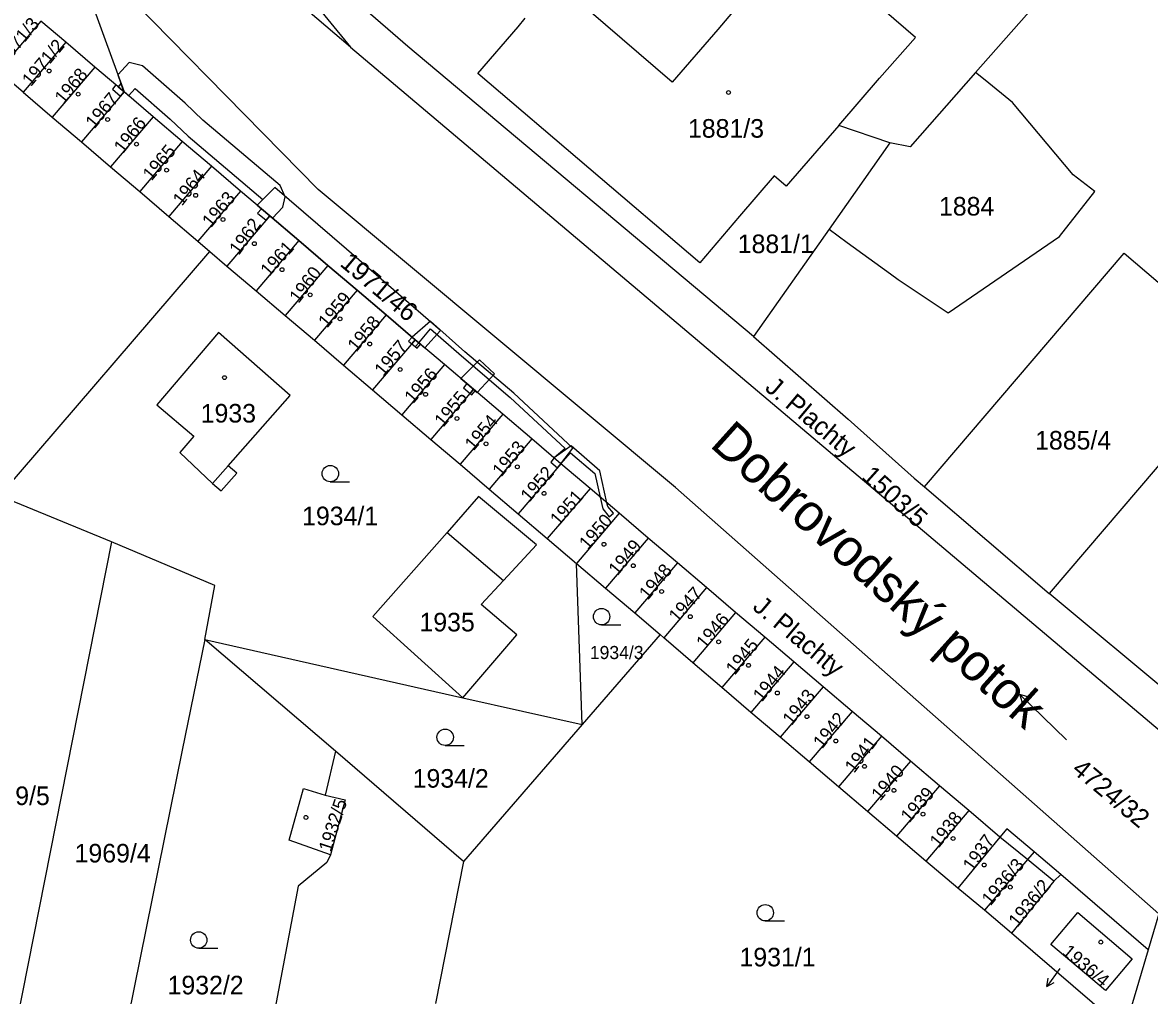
# Model space of a CAD drawing. Extents: x -756746 to -753363, y -1166406 to -1161727.
# Drawn here: x -755238.8 to -755135.8, y -1164912.5 to -1164823.5 of the extents above; entities that cross this region are included whole.
import ezdxf

# ---------------------------------------------------------------- set-up
doc = ezdxf.new("R2010")
doc.units = 0
for name, color, linetype in [('Hranice parcel', 7, 'Continuous'), ('Parcelní čísla', 7, 'Continuous'), ('Pop  PČ popisy', 7, 'Continuous'), ('Vnitřní kresba', 7, 'Continuous'), ('Věcná břemena k části', 7, 'Continuous'), ('Značky budov', 7, 'Continuous'), ('Značky kultur', 7, 'Continuous')]:
    doc.layers.add(name, color=color, linetype=linetype)

msp = doc.modelspace()

# ---------------------------------------------------------------- linework, layer by layer
at = {"layer": 'Hranice parcel'}
for p, q in [((-755208.84, -1164825.74), (-755252.46, -1164788.39)), ((-755137.74, -1164812.25), (-755151.68, -1164828.07)), ((-755203.59, -1164825.69), (-755207.92, -1164821.92)), ((-755237.14, -1164823.35), (-755241.04, -1164827.93)), ((-755234.87, -1164825.3), (-755237.14, -1164823.35)), ((-755193.52, -1164823.87), (-755192.86, -1164823.09)), ((-755234.87, -1164825.3), (-755238.76, -1164829.87)), ((-755232.2, -1164827.57), (-755234.87, -1164825.3)), ((-755172, -1164852.19), (-755203.59, -1164825.69)), ((-755238.76, -1164829.87), (-755241.04, -1164827.93)), ((-755232.2, -1164827.57), (-755236.1, -1164832.14)), ((-755229.54, -1164829.83), (-755232.2, -1164827.57)), ((-755238.76, -1164829.87), (-755236.1, -1164832.14)), ((-755229.54, -1164829.83), (-755233.43, -1164834.41)), ((-755226.88, -1164832.1), (-755229.54, -1164829.83)), ((-755236.1, -1164832.14), (-755233.43, -1164834.41)), ((-755226.88, -1164832.1), (-755230.77, -1164836.68)), ((-755224.21, -1164834.37), (-755226.88, -1164832.1)), ((-755159.51, -1164834.5), (-755164.19, -1164832.9)), ((-755233.43, -1164834.41), (-755230.77, -1164836.68)), ((-755224.21, -1164834.37), (-755228.11, -1164838.95)), ((-755221.55, -1164836.63), (-755224.21, -1164834.37)), ((-755159.51, -1164834.5), (-755165.07, -1164842.38)), ((-755230.77, -1164836.68), (-755228.11, -1164838.95)), ((-755221.55, -1164836.63), (-755225.45, -1164841.22)), ((-755218.89, -1164838.9), (-755221.55, -1164836.63)), ((-755228.11, -1164838.95), (-755225.45, -1164841.22)), ((-755218.89, -1164838.9), (-755222.79, -1164843.49)), ((-755216.22, -1164841.17), (-755218.89, -1164838.9)), ((-755225.45, -1164841.22), (-755222.79, -1164843.49)), ((-755216.22, -1164841.17), (-755220.13, -1164845.76)), ((-755213.56, -1164843.43), (-755216.22, -1164841.17)), ((-755165.07, -1164842.38), (-755172, -1164852.19)), ((-755222.79, -1164843.49), (-755221.69, -1164844.43)), ((-755213.56, -1164843.43), (-755217.47, -1164848.02)), ((-755210.9, -1164845.7), (-755213.56, -1164843.43)), ((-755240.86, -1164866.75), (-755221.69, -1164844.43)), ((-755221.69, -1164844.43), (-755220.13, -1164845.76)), ((-755220.13, -1164845.76), (-755217.47, -1164848.02)), ((-755210.9, -1164845.7), (-755214.8, -1164850.29)), ((-755208.24, -1164847.97), (-755210.9, -1164845.7)), ((-755217.47, -1164848.02), (-755214.8, -1164850.29)), ((-755208.24, -1164847.97), (-755212.14, -1164852.55)), ((-755205.57, -1164850.23), (-755208.24, -1164847.97)), ((-755214.8, -1164850.29), (-755212.14, -1164852.55)), ((-755205.57, -1164850.23), (-755209.48, -1164854.82)), ((-755202.91, -1164852.5), (-755205.57, -1164850.23)), ((-755212.14, -1164852.55), (-755209.48, -1164854.82)), ((-755202.91, -1164852.5), (-755206.81, -1164857.09)), ((-755200.25, -1164854.76), (-755202.91, -1164852.5)), ((-755209.48, -1164854.82), (-755206.81, -1164857.09)), ((-755200.25, -1164854.76), (-755204.15, -1164859.35)), ((-755197.58, -1164857.03), (-755200.25, -1164854.76)), ((-755126.69, -1164854.3), (-755144.95, -1164875.7)), ((-755206.81, -1164857.09), (-755204.15, -1164859.35)), ((-755197.58, -1164857.03), (-755201.49, -1164861.62)), ((-755194.92, -1164859.3), (-755197.58, -1164857.03)), ((-755204.15, -1164859.35), (-755201.49, -1164861.62)), ((-755194.92, -1164859.3), (-755198.82, -1164863.89)), ((-755192.26, -1164861.56), (-755194.92, -1164859.3)), ((-755201.49, -1164861.62), (-755198.82, -1164863.89)), ((-755192.26, -1164861.56), (-755196.16, -1164866.15)), ((-755189.6, -1164863.83), (-755192.26, -1164861.56)), ((-755198.82, -1164863.89), (-755196.16, -1164866.15)), ((-755189.6, -1164863.83), (-755193.5, -1164868.42)), ((-755186.93, -1164866.1), (-755189.6, -1164863.83)), ((-755196.16, -1164866.15), (-755193.5, -1164868.42)), ((-755186.93, -1164866.1), (-755190.84, -1164870.68)), ((-755184.27, -1164868.36), (-755186.93, -1164866.1)), ((-755156.36, -1164865.96), (-755144.95, -1164875.7)), ((-755230.7, -1164870.97), (-755240.62, -1164866.88)), ((-755193.5, -1164868.42), (-755190.84, -1164870.68)), ((-755184.27, -1164868.36), (-755188.17, -1164872.95)), ((-755181.61, -1164870.63), (-755184.27, -1164868.36)), ((-755230.7, -1164870.97), (-755239.99, -1164918.1)), ((-755190.84, -1164870.68), (-755188.17, -1164872.95)), ((-755181.61, -1164870.63), (-755185.51, -1164875.22)), ((-755178.94, -1164872.9), (-755181.61, -1164870.63)), ((-755188.17, -1164872.95), (-755185.51, -1164875.22)), ((-755187.65, -1164887.69), (-755188.17, -1164872.95)), ((-755178.94, -1164872.9), (-755182.85, -1164877.48)), ((-755176.28, -1164875.16), (-755178.94, -1164872.9)), ((-755185.51, -1164875.22), (-755182.85, -1164877.48)), ((-755176.28, -1164875.16), (-755180.19, -1164879.75)), ((-755173.62, -1164877.43), (-755176.28, -1164875.16)), ((-755125.85, -1164891.66), (-755144.95, -1164875.7)), ((-755182.85, -1164877.48), (-755180.52, -1164879.46)), ((-755173.62, -1164877.43), (-755177.54, -1164882.04)), ((-755170.95, -1164879.7), (-755173.62, -1164877.43)), ((-755180.52, -1164879.46), (-755187.65, -1164887.69)), ((-755180.19, -1164879.75), (-755180.52, -1164879.46)), ((-755210.2, -1164890.12), (-755222.16, -1164879.9)), ((-755222.16, -1164879.9), (-755198.55, -1164885.23)), ((-755177.54, -1164882.04), (-755180.19, -1164879.75)), ((-755170.95, -1164879.7), (-755174.88, -1164884.31)), ((-755168.29, -1164881.96), (-755170.95, -1164879.7)), ((-755174.88, -1164884.31), (-755177.54, -1164882.04)), ((-755168.29, -1164881.96), (-755172.22, -1164886.57)), ((-755165.63, -1164884.23), (-755168.29, -1164881.96)), ((-755172.22, -1164886.57), (-755174.88, -1164884.31)), ((-755165.63, -1164884.23), (-755169.55, -1164888.84)), ((-755162.96, -1164886.5), (-755165.63, -1164884.23)), ((-755198.55, -1164885.23), (-755187.65, -1164887.69)), ((-755169.55, -1164888.84), (-755172.22, -1164886.57)), ((-755162.96, -1164886.5), (-755166.89, -1164891.11)), ((-755160.3, -1164888.76), (-755162.96, -1164886.5)), ((-755187.65, -1164887.69), (-755198.5, -1164900.22)), ((-755166.89, -1164891.11), (-755169.55, -1164888.84)), ((-755160.3, -1164888.76), (-755164.23, -1164893.37)), ((-755157.64, -1164891.03), (-755160.3, -1164888.76)), ((-755210.2, -1164890.12), (-755211.16, -1164894.14)), ((-755198.5, -1164900.22), (-755210.2, -1164890.12)), ((-755164.23, -1164893.37), (-755166.89, -1164891.11)), ((-755157.64, -1164891.03), (-755161.56, -1164895.64)), ((-755154.98, -1164893.29), (-755157.64, -1164891.03)), ((-755161.56, -1164895.64), (-755164.23, -1164893.37)), ((-755154.98, -1164893.29), (-755158.9, -1164897.9)), ((-755152.31, -1164895.56), (-755154.98, -1164893.29)), ((-755158.9, -1164897.9), (-755161.56, -1164895.64)), ((-755152.31, -1164895.56), (-755156.24, -1164900.17)), ((-755149.46, -1164897.99), (-755152.31, -1164895.56)), ((-755156.24, -1164900.17), (-755158.9, -1164897.9)), ((-755149.46, -1164897.99), (-755153.31, -1164902.66)), ((-755148.82, -1164897.21), (-755149.46, -1164897.99)), ((-755146.34, -1164899.32), (-755148.82, -1164897.21)), ((-755153.31, -1164902.66), (-755156.24, -1164900.17)), ((-755143.9, -1164901.41), (-755146.34, -1164899.32)), ((-755198.5, -1164900.22), (-755201.07, -1164913.21)), ((-755135.91, -1164908.29), (-755143.9, -1164901.41)), ((-755150.86, -1164904.67), (-755153.31, -1164902.66)), ((-755148.4, -1164906.75), (-755150.86, -1164904.67)), ((-755134.94, -1164904.99), (-755135.91, -1164908.29)), ((-755138.07, -1164915.62), (-755148.4, -1164906.75)), ((-755135.91, -1164908.29), (-755138.07, -1164915.62))]:
    msp.add_line(p, q, dxfattribs=at)
for points in [[(-755219.59, -1164811.74), (-755216.58, -1164816.25), (-755208.84, -1164825.74)], [(-755164.19, -1164832.9), (-755160.46, -1164828.59), (-755157.19, -1164824.86), (-755167.97, -1164815.54), (-755171.21, -1164819.3), (-755175.25, -1164824.14), (-755179.43, -1164828.93), (-755188.58, -1164821.04)], [(-755134.94, -1164904.99), (-755179.12, -1164866), (-755211.8, -1164838.76), (-755233.7, -1164816.4)], [(-755233.7, -1164816.4), (-755233, -1164820.27), (-755231.4, -1164824.73), (-755229.54, -1164829.83)], [(-755164.19, -1164832.9), (-755169, -1164838.46), (-755170.11, -1164837.51), (-755173.26, -1164841.2), (-755176.91, -1164845.47), (-755197.19, -1164828.14), (-755193.52, -1164823.87)], [(-755208.84, -1164825.74), (-755127.96, -1164894.05), (-755102.91, -1164910.48), (-755089.38, -1164916.68), (-755079.72, -1164919.29), (-755073.75, -1164919.95), (-755066.23, -1164919.84)], [(-755165.07, -1164842.38), (-755163.41, -1164843.59), (-755159.47, -1164846.46), (-755158.75, -1164846.99), (-755154.18, -1164850.05), (-755144.02, -1164843.07), (-755140.77, -1164838.95), (-755142.75, -1164837.43), (-755148.3, -1164830.79), (-755150.8, -1164828.77), (-755151.68, -1164828.07)], [(-755151.68, -1164828.07), (-755157.66, -1164834.87), (-755159.51, -1164834.5)], [(-755156.36, -1164865.96), (-755138.1, -1164844.57), (-755126.69, -1164854.3)], [(-755214.36, -1164857.59), (-755220.89, -1164851.84), (-755226.55, -1164858.45)], [(-755172, -1164852.19), (-755163.34, -1164859.75), (-755157.31, -1164865.16), (-755156.36, -1164865.96)], [(-755226.55, -1164858.45), (-755223.17, -1164861.33), (-755224.45, -1164862.82), (-755221.45, -1164865.63), (-755220.67, -1164866.32), (-755219.24, -1164864.7), (-755220.03, -1164864.03), (-755214.36, -1164857.59)], [(-755206.8, -1164877.81), (-755198.55, -1164885.23), (-755193.64, -1164879.48), (-755196.88, -1164876.71), (-755194.85, -1164874.51), (-755191.84, -1164871.26), (-755197.14, -1164866.83), (-755200, -1164870.13), (-755206.8, -1164877.81)], [(-755222.16, -1164879.9), (-755221.25, -1164874.96), (-755230.7, -1164870.97)], [(-755222.16, -1164879.9), (-755224.21, -1164890.04), (-755229.72, -1164917.15)], [(-755210.67, -1164899.6), (-755214.45, -1164898.27), (-755213.12, -1164893.53), (-755211.16, -1164894.14)], [(-755211.16, -1164894.14), (-755209.33, -1164894.56), (-755210.67, -1164899.6)], [(-755210.67, -1164899.6), (-755211, -1164900.31), (-755213.61, -1164902.48)], [(-755146.34, -1164899.32), (-755146.93, -1164900.02), (-755150.86, -1164904.67)], [(-755143.9, -1164901.41), (-755144.54, -1164902.01), (-755148.4, -1164906.75)], [(-755213.61, -1164902.48), (-755217.42, -1164922.61), (-755217.08, -1164926.2)], [(-755139.82, -1164912.02), (-755144.8, -1164907.79), (-755142.33, -1164904.88), (-755137.37, -1164909.12), (-755139.82, -1164912.02)]]:
    msp.add_lwpolyline(points, dxfattribs=at)
at = {"layer": 'Pop  PČ popisy'}
for p, q in [((-755143.98, -1164910), (-755145.16, -1164911.63)), ((-755145.16, -1164911.63), (-755145.04, -1164910.89)), ((-755145.16, -1164911.63), (-755144.5, -1164911.28))]:
    msp.add_line(p, q, dxfattribs=at)
at = {"layer": 'Vnitřní kresba'}
for p, q in [((-755221.45, -1164865.63), (-755220.03, -1164864.03)), ((-755200, -1164870.13), (-755194.85, -1164874.51)), ((-755146.93, -1164900.02), (-755149.46, -1164897.99)), ((-755144.54, -1164902.01), (-755146.93, -1164900.02))]:
    msp.add_line(p, q, dxfattribs=at)
at = {"layer": 'Věcná břemena k části'}
for points in [[(-755215.03, -1164840.38), (-755214.82, -1164839.44), (-755215.27, -1164838.39), (-755222.35, -1164832.41), (-755223.95, -1164830.85), (-755227.84, -1164827.45), (-755229.08, -1164827.13), (-755230.11, -1164828.27), (-755229.82, -1164829.05), (-755229.54, -1164829.83), (-755229.13, -1164830.18), (-755228.53, -1164829.51), (-755225.31, -1164832.33), (-755223.69, -1164833.89), (-755216.84, -1164839.68), (-755217.36, -1164840.2), (-755216.22, -1164841.17), (-755215.97, -1164841.38)], [(-755230.08, -1164829.37), (-755229.54, -1164829.83), (-755229.82, -1164829.05)], [(-755229.54, -1164829.83), (-755230.08, -1164829.37), (-755230.29, -1164829.2), (-755230.61, -1164829.58), (-755229.86, -1164830.21)], [(-755217.36, -1164840.2), (-755216.98, -1164840.52), (-755216.22, -1164841.17), (-755213.56, -1164843.43), (-755210.9, -1164845.7), (-755208.24, -1164847.97), (-755205.57, -1164850.23), (-755202.91, -1164852.5), (-755202.43, -1164852.91), (-755202.05, -1164853.23), (-755200.6, -1164851.65), (-755209.2, -1164844.22), (-755215.74, -1164838.58)], [(-755216.22, -1164841.17), (-755216.98, -1164840.52), (-755217.34, -1164840.91), (-755216.56, -1164841.57)], [(-755201.51, -1164851.49), (-755198.69, -1164853.98), (-755194.23, -1164857.77), (-755189.21, -1164862.44), (-755190.21, -1164863.31), (-755189.6, -1164863.83), (-755188.51, -1164862.4), (-755193.89, -1164857.39), (-755198.37, -1164853.6), (-755201.53, -1164850.81), (-755203.2, -1164852.25), (-755202.59, -1164852.77)], [(-755203.52, -1164852.63), (-755203.23, -1164852.88), (-755202.91, -1164852.5), (-755203.2, -1164852.25)], [(-755202.59, -1164852.77), (-755202.91, -1164852.5), (-755203.23, -1164852.88), (-755202.92, -1164853.15)], [(-755202.43, -1164852.91), (-755202.91, -1164852.5), (-755203.22, -1164852.87), (-755202.75, -1164853.27)], [(-755198.19, -1164856.51), (-755197.43, -1164857.16), (-755197.24, -1164857.32), (-755195.67, -1164855.61), (-755197.03, -1164854.32), (-755198.74, -1164856.04)], [(-755198.51, -1164856.89), (-755197.9, -1164857.41), (-755197.58, -1164857.03), (-755198.19, -1164856.51)], [(-755197.43, -1164857.16), (-755197.58, -1164857.03), (-755197.9, -1164857.41), (-755197.75, -1164857.54)], [(-755188.71, -1164862.83), (-755186.5, -1164864.74), (-755186.02, -1164866.88), (-755185.77, -1164867.97), (-755185.17, -1164868.69), (-755184.79, -1164868.37), (-755185.31, -1164867.75), (-755185.39, -1164867.41), (-755186.04, -1164864.48), (-755188.67, -1164862.19), (-755190.21, -1164863.31), (-755189.6, -1164863.83)], [(-755189.92, -1164864.21), (-755189.6, -1164863.83), (-755190.21, -1164863.31), (-755190.53, -1164863.69)]]:
    msp.add_lwpolyline(points, close=True, dxfattribs=at)
at = {"layer": 'Značky budov'}
for centre in [(-755236.38, -1164827.92), (-755233.73, -1164830.04), (-755174.28, -1164829.89), (-755231.04, -1164832.36), (-755228.4, -1164834.61), (-755225.65, -1164836.99), (-755222.99, -1164839.29), (-755220.49, -1164841.5), (-755217.62, -1164843.71), (-755215.09, -1164846.09), (-755212.52, -1164848.39), (-755209.79, -1164850.58), (-755207.08, -1164852.88), (-755220.35, -1164855.96), (-755204.29, -1164855.22), (-755201.97, -1164857.49), (-755199.1, -1164859.7), (-755196.44, -1164862.02), (-755193.58, -1164864.12), (-755191.14, -1164866.55), (-755185.66, -1164871.2), (-755182.98, -1164873.16), (-755180.39, -1164875.52), (-755177.77, -1164877.82), (-755175.18, -1164880.12), (-755172.45, -1164882.27), (-755169.81, -1164884.8), (-755167.1, -1164886.96), (-755164.46, -1164889.19), (-755161.84, -1164891.51), (-755159.15, -1164893.71), (-755212.91, -1164896.18), (-755156.49, -1164895.88), (-755153.74, -1164898.11), (-755150.9, -1164900.53), (-755148.51, -1164902.55), (-755140.23, -1164907.58)]:
    msp.add_circle(centre, 0.175, dxfattribs=at)
at = {"layer": 'Značky kultur'}
for p, q in [((-755210.68, -1164865.49), (-755208.93, -1164865.49)), ((-755185.88, -1164878.57), (-755184.13, -1164878.57)), ((-755143.37, -1164889.07), (-755147.68, -1164884.9)), ((-755147.68, -1164884.9), (-755147.33, -1164885.94)), ((-755147.68, -1164884.9), (-755146.63, -1164885.22)), ((-755200.18, -1164889.6), (-755198.43, -1164889.6)), ((-755170.91, -1164905.65), (-755169.16, -1164905.65)), ((-755222.71, -1164908.14), (-755220.96, -1164908.14))]:
    msp.add_line(p, q, dxfattribs=at)
for centre in [(-755210.68, -1164864.74), (-755185.88, -1164877.82), (-755200.18, -1164888.85), (-755170.91, -1164904.9), (-755222.71, -1164907.39)]:
    msp.add_circle(centre, 0.75, dxfattribs=at)

# ---------------------------------------------------------------- texts
at = {"layer": 'Parcelní čísla'}
for s, height, rotation, p in [('1971/3', 1.2, 50, (-755240.37, -1164827.42)), ('1971/2', 1.2, 50, (-755238.06, -1164829.41)), ('1968', 1.2, 50, (-755235.08, -1164831.02)), ('1967', 1.2, 50, (-755232.26, -1164833.27)), ('1966', 1.2, 52, (-755229.63, -1164835.53)), ('1965', 1.2, 50, (-755227.03, -1164838.03)), ('1964', 1.2, 52, (-755224.24, -1164840.32)), ('1963', 1.2, 50, (-755221.59, -1164842.31)), ('1962', 1.2, 54, (-755219.05, -1164844.83)), ('1961', 1.2, 48, (-755216.3, -1164846.8)), ('1971/46', 1.7, 320, (-755209.89, -1164845.67)), ('1960', 1.2, 53, (-755213.58, -1164849.23)), ('1959', 1.2, 50, (-755210.98, -1164851.49)), ('1958', 1.2, 50, (-755208.3, -1164853.67)), ('1957', 1.2, 50, (-755205.84, -1164855.91)), ('1956', 1.2, 49, (-755203.12, -1164858.41)), ('1955', 1.2, 50, (-755200.36, -1164860.56)), ('1954', 1.2, 50, (-755197.58, -1164862.71)), ('1953', 1.2, 50, (-755195.06, -1164865.11)), ('1952', 1.2, 49, (-755192.5, -1164867.42)), ('1503/5', 1.7, 318, (-755162.2, -1164865.13)), ('1951', 1.2, 49, (-755189.8, -1164869.58)), ('1950', 1.2, 49, (-755187.15, -1164871.78)), ('1949', 1.2, 50, (-755184.44, -1164874.14)), ('1948', 1.2, 50, (-755181.65, -1164876.36)), ('1947', 1.2, 48, (-755178.97, -1164878.43)), ('1946', 1.2, 50, (-755176.42, -1164880.84)), ('1945', 1.2, 51, (-755173.7, -1164883.23)), ('1944', 1.2, 51, (-755171.22, -1164885.68)), ('1943', 1.2, 51, (-755168.51, -1164887.84)), ('1942', 1.2, 51, (-755165.71, -1164889.96)), ('1941', 1.2, 53, (-755162.79, -1164892.19)), ('1940', 1.2, 50, (-755160.41, -1164894.74)), ('4724/32', 1.7, 320, (-755142.98, -1164891.97)), ('1939', 1.2, 48, (-755157.76, -1164896.73)), ('1932/5', 1.2, 72, (-755210.64, -1164899.4)), ('1938', 1.2, 51, (-755155.06, -1164899.03)), ('1937', 1.2, 54, (-755151.99, -1164901.19)), ('1936/3', 1.2, 50, (-755150.32, -1164904.32)), ('1936/2', 1.2, 51, (-755147.85, -1164906.28)), ('1936/4', 1.2, 320, (-755143.85, -1164908.61))]:
    msp.add_text(s, height=height, rotation=rotation, dxfattribs=at).set_placement(p)
for s, height, p in [('1881/3', 1.7, (-755177.98, -1164834.02)), ('1884', 1.7, (-755155.03, -1164841.14)), ('1881/1', 1.7, (-755173.43, -1164844.58)), ('1933', 1.7, (-755222.53, -1164860.07)), ('1885/4', 1.7, (-755146.24, -1164862.54)), ('1934/1', 1.7, (-755213.26, -1164869.46)), ('1935', 1.7, (-755202.53, -1164879.17)), ('1934/3', 1.2, (-755186.95, -1164881.7)), ('1934/2', 1.7, (-755203.15, -1164893.46)), ('1969/5', 1.7, (-755243.28, -1164895.05)), ('1969/4', 1.7, (-755234.06, -1164900.3)), ('1931/1', 1.7, (-755173.27, -1164909.8)), ('1932/2', 1.7, (-755225.56, -1164912.36))]:
    msp.add_text(s, height=height, dxfattribs=at).set_placement(p)
at = {"layer": 'Pop  PČ popisy'}
for s, height, rotation, p in [('J. Plachty', 1.7, 320, (-755171.04, -1164857.04)), ('Dobrovodský potok', 3.4, 318, (-755176.08, -1164862.2)), ('J. Plachty', 1.7, 320, (-755172.17, -1164877.08))]:
    msp.add_text(s, height=height, rotation=rotation, dxfattribs=at).set_placement(p)

doc.saveas('drawing.dxf')
